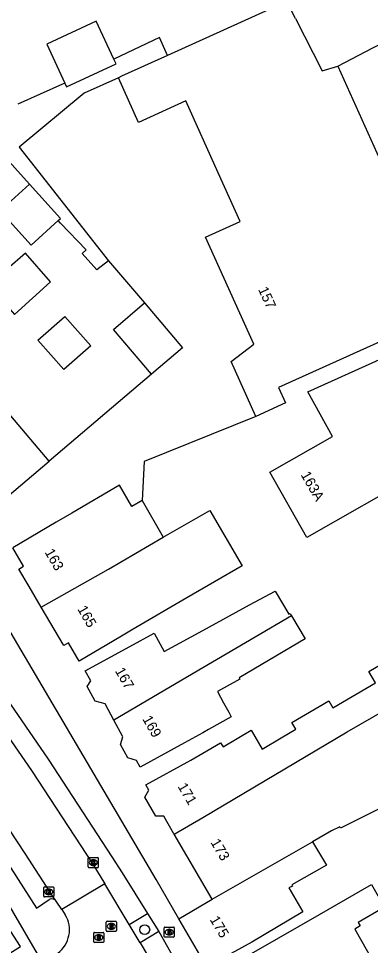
# Model space of a CAD drawing. Extents: x 159888 to 160757, y 384031 to 384746.
# Drawn here: x 160481.8 to 160516.6, y 384336.2 to 384427.7 of the extents above; entities that cross this region are included whole.
import ezdxf

# ---------------------------------------------------------------- set-up
doc = ezdxf.new("R2010")
doc.units = 0
for name, color, linetype in [('IMGEO_Boom', 7, 'Continuous'), ('IMGEO_Brandkraan', 7, 'Continuous'), ('IMGEO_Kolk', 7, 'Continuous'), ('IMGEO_Pand', 7, 'Continuous'), ('IMGEO_Pand_nummerreeks', 7, 'Continuous'), ('IMGEO_Parkeervlak_open', 7, 'Continuous'), ('IMGEO_Rijbaan_lokaal_open', 7, 'Continuous'), ('IMGEO_Rioolput', 7, 'Continuous'), ('IMGEO_Voetpad_open', 7, 'Continuous')]:
    doc.layers.add(name, color=color, linetype=linetype)

msp = doc.modelspace()

# ---------------------------------------------------------------- linework, layer by layer
at = {"layer": 'IMGEO_Boom'}
msp.add_circle((160494.244, 384337.788), 0.489, dxfattribs=at)
at = {"layer": 'IMGEO_Brandkraan'}
for p, q in [((160496.165, 384337.121), (160496.165, 384337.973)), ((160496.24, 384338.047), (160497.092, 384338.047)), ((160496.653, 384337.827), (160496.678, 384337.827)), ((160497.166, 384337.973), (160497.166, 384337.121)), ((160497.092, 384337.047), (160496.24, 384337.047)), ((160496.676, 384337.267), (160496.651, 384337.267))]:
    msp.add_line(p, q, dxfattribs=at)
for points in [[(160496.165, 384337.121), (160496.165, 384337.973)], [(160496.24, 384338.047), (160497.092, 384338.047)], [(160496.513, 384337.747), (160496.513, 384337.347), (160496.726, 384337.347)], [(160496.744, 384337.747), (160496.513, 384337.747)], [(160496.692, 384337.666), (160496.638, 384337.666), (160496.638, 384337.59)], [(160496.638, 384337.59), (160496.691, 384337.59)], [(160496.7, 384337.514), (160496.638, 384337.514), (160496.638, 384337.433)], [(160496.638, 384337.433), (160496.7, 384337.433)], [(160497.166, 384337.973), (160497.166, 384337.121)], [(160497.092, 384337.047), (160496.24, 384337.047)]]:
    msp.add_lwpolyline(points, dxfattribs=at)
for centre, radius, start, end in [((160496.242, 384337.971), 0.0765, 91.55205, 178.44795), ((160496.242, 384337.971), 0.0765, 91.55205, 178.44795), ((160496.693, 384337.628), 0.0379, 267.82845, 90.93552), ((160496.701, 384337.473), 0.0404, 269.87594, 90.50774), ((160496.748, 384337.602), 0.145, 59.4692, 91.53667), ((160496.773, 384337.649), 0.0922, 285.51372, 58.15012), ((160496.778, 384337.457), 0.105, 301.31148, 78.98903), ((160497.09, 384337.971), 0.0765, 1.55205, 88.44795), ((160497.09, 384337.971), 0.0765, 1.55205, 88.44795), ((160496.242, 384337.123), 0.0765, 181.55205, 268.44795), ((160496.242, 384337.123), 0.0765, 181.55205, 268.44795), ((160496.732, 384337.598), 0.251, 268.66757, 293.53466), ((160497.09, 384337.123), 0.0765, 271.55205, 358.44795), ((160497.09, 384337.123), 0.0765, 271.55205, 358.44795)]:
    msp.add_arc(centre, radius, start, end, dxfattribs=at)
for centre, major_axis, ratio, start_param, end_param in [((160496.652, 384337.547), (-0.387, 0.002), 0.722429, 4.712389, 7.853982), ((160496.677, 384337.547), (-0.39, 0.002), 0.717154, 1.570796, 4.712389)]:
    msp.add_ellipse(centre, major_axis=major_axis, ratio=ratio, start_param=start_param, end_param=end_param, dxfattribs=at)
at = {"layer": 'IMGEO_Kolk'}
for p, q in [((160488.659, 384343.984), (160488.659, 384344.836)), ((160488.734, 384344.91), (160489.586, 384344.91)), ((160489.66, 384344.836), (160489.66, 384343.984)), ((160489.586, 384343.91), (160488.734, 384343.91)), ((160489.17, 384344.13), (160489.145, 384344.13)), ((160489.147, 384344.69), (160489.172, 384344.69)), ((160484.336, 384342.021), (160485.188, 384342.021)), ((160484.261, 384341.095), (160484.261, 384341.947)), ((160484.772, 384341.241), (160484.747, 384341.241)), ((160484.749, 384341.801), (160484.774, 384341.801)), ((160485.262, 384341.947), (160485.262, 384341.095)), ((160485.188, 384341.021), (160484.336, 384341.021))]:
    msp.add_line(p, q, dxfattribs=at)
for points in [[(160488.659, 384343.984), (160488.659, 384344.836)], [(160488.734, 384344.91), (160489.586, 384344.91)], [(160489.66, 384344.836), (160489.66, 384343.984)], [(160489.586, 384343.91), (160488.734, 384343.91)], [(160488.98, 384344.61), (160489.103, 384344.61), (160489.103, 384344.459), (160489.233, 384344.61), (160489.397, 384344.61), (160489.251, 384344.459), (160489.404, 384344.21), (160489.252, 384344.21), (160489.167, 384344.374), (160489.103, 384344.307), (160489.103, 384344.21), (160488.98, 384344.21), (160488.98, 384344.61)], [(160484.336, 384342.021), (160485.188, 384342.021)], [(160484.261, 384341.095), (160484.261, 384341.947)], [(160484.582, 384341.721), (160484.705, 384341.721), (160484.705, 384341.57), (160484.835, 384341.721), (160484.999, 384341.721), (160484.853, 384341.57), (160485.006, 384341.321), (160484.854, 384341.321), (160484.769, 384341.485), (160484.705, 384341.418), (160484.705, 384341.321), (160484.582, 384341.321), (160484.582, 384341.721)], [(160485.262, 384341.947), (160485.262, 384341.095)], [(160485.188, 384341.021), (160484.336, 384341.021)]]:
    msp.add_lwpolyline(points, dxfattribs=at)
for centre, start, end in [((160488.736, 384344.834), 91.55205, 178.44795), ((160488.736, 384344.834), 91.55205, 178.44795), ((160489.584, 384344.834), 1.55205, 88.44795), ((160489.584, 384344.834), 1.55205, 88.44795), ((160488.736, 384343.986), 181.55205, 268.44795), ((160488.736, 384343.986), 181.55205, 268.44795), ((160489.584, 384343.986), 271.55205, 358.44795), ((160489.584, 384343.986), 271.55205, 358.44795), ((160484.338, 384341.945), 91.55205, 178.44795), ((160484.338, 384341.945), 91.55205, 178.44795), ((160485.186, 384341.945), 1.55205, 88.44795), ((160485.186, 384341.945), 1.55205, 88.44795), ((160484.338, 384341.097), 181.55205, 268.44795), ((160484.338, 384341.097), 181.55205, 268.44795), ((160485.186, 384341.097), 271.55205, 358.44795), ((160485.186, 384341.097), 271.55205, 358.44795)]:
    msp.add_arc(centre, 0.0765, start, end, dxfattribs=at)
for centre, major_axis, ratio, start_param, end_param in [((160489.146, 384344.41), (-0.387, 0.002), 0.722429, 4.712389, 7.853982), ((160489.171, 384344.41), (-0.39, 0.002), 0.717154, 1.570796, 4.712389), ((160484.748, 384341.521), (-0.387, 0.002), 0.722429, 4.712389, 7.853982), ((160484.773, 384341.521), (-0.39, 0.002), 0.717154, 1.570796, 4.712389)]:
    msp.add_ellipse(centre, major_axis=major_axis, ratio=ratio, start_param=start_param, end_param=end_param, dxfattribs=at)
at = {"layer": 'IMGEO_Pand'}
for points in [[(160509.129, 384427.751), (160508.248, 384429.476), (160507.911, 384429.24), (160496.507, 384424.091)], [(160491.204, 384423.709), (160489.455, 384427.481), (160484.568, 384425.214), (160486.351, 384421.37)], [(160509.129, 384427.751), (160511.769, 384422.587), (160513.319, 384423.031)], [(160513.319, 384423.031), (160516.785, 384424.832), (160519.049, 384426.008)], [(160486.351, 384421.37), (160486.528, 384420.988), (160491.415, 384423.255), (160491.204, 384423.709)], [(160496.507, 384424.091), (160491.96, 384422.038), (160491.637, 384421.892)], [(160513.319, 384423.031), (160517.476, 384413.822)], [(160505.218, 384388.461), (160502.777, 384393.869), (160505.018, 384395.587), (160500.243, 384406.162), (160503.674, 384407.711), (160501.513, 384412.497), (160498.306, 384419.599), (160493.626, 384417.486), (160491.637, 384421.892)], [(160485.695, 384407.79), (160483.023, 384405.371), (160479.952, 384408.762), (160482.855, 384411.39)], [(160485.695, 384407.79), (160485.926, 384407.999), (160482.855, 384411.39)], [(160478.811, 384401.423), (160481.368, 384398.511), (160484.946, 384401.73), (160482.458, 384404.564), (160478.811, 384401.423)], [(160494.904, 384392.62), (160491.151, 384397.042), (160494.231, 384399.656)], [(160494.231, 384399.656), (160497.984, 384395.234), (160494.904, 384392.62)], [(160486.347, 384398.321), (160488.903, 384395.409), (160486.244, 384393.074), (160483.687, 384395.986), (160486.347, 384398.321)], [(160528.944, 384398.447), (160531.06, 384394.011), (160529.854, 384393.381), (160532.476, 384389.133), (160510.261, 384376.495), (160506.59, 384382.948), (160512.814, 384386.489), (160510.357, 384390.876), (160520.089, 384395.264), (160520.242, 384394.924), (160522.66, 384396.015)], [(160522.66, 384396.015), (160521.851, 384397.809), (160507.479, 384391.32), (160508.168, 384389.793), (160505.218, 384388.461)], [(160484.795, 384384.039), (160481.004, 384388.519)], [(160475.174, 384375.922), (160484.795, 384384.039)], [(160493.992, 384380.172), (160492.963, 384379.573), (160491.751, 384381.655), (160487.049, 384378.918), (160485.49, 384378.011), (160481.206, 384375.483)], [(160493.992, 384380.172), (160496.065, 384376.531)], [(160496.065, 384376.531), (160500.691, 384379.183), (160503.875, 384373.713), (160498.413, 384370.534), (160493.098, 384367.44), (160491.959, 384366.777), (160487.774, 384364.286), (160486.707, 384366.106), (160486.241, 384365.833), (160484.01, 384369.637)], [(160484.01, 384369.637), (160490.663, 384373.365), (160496.065, 384376.531)], [(160484.01, 384369.637), (160482.825, 384371.656), (160481.808, 384373.39), (160482.274, 384373.663), (160481.206, 384375.483)], [(160491.205, 384358.458), (160490.321, 384360.076), (160489.362, 384360.357), (160488.572, 384361.803), (160488.911, 384362.359), (160488.37, 384363.35), (160492.759, 384365.747), (160495.173, 384367.066), (160496.173, 384365.235), (160500, 384367.326), (160504.611, 384369.845), (160507.136, 384371.221), (160508.499, 384368.935), (160508.613, 384369.002), (160508.754, 384368.765)], [(160508.754, 384368.765), (160510.108, 384366.495), (160503.576, 384362.635), (160503.641, 384362.517), (160501.427, 384361.308), (160502.033, 384360.198), (160502.553, 384359.247), (160502.799, 384358.796), (160500.557, 384357.541), (160500, 384357.237), (160498.176, 384356.241), (160493.788, 384353.843), (160493.428, 384354.502), (160492.576, 384354.752), (160491.86, 384356.064), (160492.088, 384356.842), (160491.205, 384358.458)], [(160508.754, 384368.765), (160505.142, 384366.671), (160502.29, 384364.99), (160500, 384363.641), (160491.205, 384358.458)], [(160524.795, 384363.386), (160533.053, 384368.196), (160537.917, 384359.917), (160535.784, 384358.855), (160513.593, 384347.808), (160513.509, 384347.952), (160512.702, 384347.561), (160510.827, 384346.464)], [(160497.158, 384347.202), (160497.136, 384347.24), (160496.126, 384348.999), (160495.356, 384348.993), (160494.254, 384350.869), (160494.651, 384351.567), (160494.342, 384352.104), (160498.816, 384354.526), (160500, 384355.222), (160501.744, 384356.246), (160501.979, 384355.846), (160504.763, 384357.481), (160505.858, 384355.619), (160507.732, 384356.72), (160509.179, 384357.57), (160508.781, 384358.247), (160512.43, 384360.391), (160512.836, 384359.7), (160517.045, 384362.172), (160516.387, 384363.292), (160522.679, 384366.989), (160524.795, 384363.386)], [(160497.158, 384347.202), (160500, 384348.872), (160514.234, 384357.32), (160524.795, 384363.386)], [(160500.922, 384340.817), (160497.158, 384347.202)], [(160510.827, 384346.464), (160512.217, 384344.158), (160508.783, 384342.211), (160508.86, 384342.098), (160508.493, 384341.916), (160509.868, 384339.538), (160504.827, 384336.564), (160500.369, 384334.119)], [(160500.922, 384340.817), (160510.827, 384346.464)], [(160500.86, 384333.269), (160503.17, 384334.51), (160507.507, 384336.999), (160511.523, 384339.303), (160516.642, 384342.24), (160517.926, 384340.003), (160515.326, 384338.512), (160515.525, 384338.164), (160514.989, 384337.856), (160516.831, 384334.645), (160514.682, 384333.412)], [(160471.677, 384337.011), (160468.334, 384334.813), (160472.553, 384328.397), (160475.896, 384330.595), (160475.071, 384331.85), (160481.974, 384336.119), (160478.474, 384341.481)], [(160497.6, 384338.863), (160500.922, 384340.817)], [(160500.369, 384334.119), (160497.6, 384338.863)]]:
    msp.add_lwpolyline(points, dxfattribs=at)
at = {"layer": 'IMGEO_Parkeervlak_open'}
for points in [[(160492.705, 384338.303), (160494.523, 384339.39)], [(160495.63, 384337.604), (160493.802, 384336.483)]]:
    msp.add_lwpolyline(points, dxfattribs=at)
at = {"layer": 'IMGEO_Rijbaan_lokaal_open'}
for points in [[(160491.637, 384421.892), (160488.271, 384420.372), (160481.828, 384415.038), (160490.66, 384403.827)], [(160490.66, 384403.827), (160494.231, 384399.656)], [(160494.904, 384392.62), (160484.795, 384384.039)], [(160505.218, 384388.461), (160494.187, 384384.008), (160493.992, 384380.172)], [(160476.066, 384363.585), (160483.044, 384353.5), (160489.12, 384344.263), (160490.303, 384342.319)], [(160485.492, 384340.604), (160485.211, 384341.033), (160482.417, 384345.31), (160479.18, 384350.228), (160475.223, 384356.099)], [(160490.303, 384342.319), (160486.063, 384339.775)], [(160492.705, 384338.303), (160490.303, 384342.319)], [(160486.063, 384339.775), (160485.492, 384340.604)], [(160486.063, 384339.775), (160486.397, 384339.266)], [(160493.802, 384336.483), (160492.705, 384338.303)], [(160493.802, 384336.483), (160495.358, 384333.901)]]:
    msp.add_lwpolyline(points, dxfattribs=at)
msp.add_arc((160483.952, 384337.783), 2.86, 306.27875, 31.241, dxfattribs=at)
at = {"layer": 'IMGEO_Rioolput'}
for p, q in [((160490.449, 384337.694), (160490.449, 384338.546)), ((160490.524, 384338.62), (160491.376, 384338.62)), ((160490.937, 384338.4), (160490.962, 384338.4)), ((160491.45, 384338.546), (160491.45, 384337.694)), ((160489.206, 384336.594), (160489.206, 384337.446)), ((160489.281, 384337.52), (160490.133, 384337.52)), ((160490.207, 384337.446), (160490.207, 384336.594)), ((160491.376, 384337.62), (160490.524, 384337.62)), ((160490.96, 384337.84), (160490.935, 384337.84)), ((160490.133, 384336.52), (160489.281, 384336.52)), ((160489.717, 384336.74), (160489.692, 384336.74)), ((160489.694, 384337.3), (160489.719, 384337.3))]:
    msp.add_line(p, q, dxfattribs=at)
for points in [[(160490.449, 384337.694), (160490.449, 384338.546)], [(160490.524, 384338.62), (160491.376, 384338.62)], [(160491.45, 384338.546), (160491.45, 384337.694)], [(160489.206, 384336.594), (160489.206, 384337.446)], [(160489.281, 384337.52), (160490.133, 384337.52)], [(160490.207, 384337.446), (160490.207, 384336.594)], [(160491.376, 384337.62), (160490.524, 384337.62)], [(160491.038, 384338.318), (160490.786, 384338.32), (160490.786, 384337.92)], [(160490.786, 384337.92), (160490.91, 384337.92), (160490.91, 384338.082), (160490.921, 384338.082)], [(160490.964, 384338.239), (160490.91, 384338.239), (160490.91, 384338.158)], [(160490.91, 384338.158), (160490.962, 384338.158)], [(160490.968, 384338.053), (160491.039, 384337.92), (160491.179, 384337.92), (160491.114, 384338.046)], [(160490.133, 384336.52), (160489.281, 384336.52)], [(160489.795, 384337.218), (160489.543, 384337.22), (160489.543, 384336.82)], [(160489.543, 384336.82), (160489.667, 384336.82), (160489.667, 384336.982), (160489.678, 384336.982)], [(160489.721, 384337.139), (160489.667, 384337.139), (160489.667, 384337.058)], [(160489.667, 384337.058), (160489.719, 384337.058)], [(160489.725, 384336.953), (160489.796, 384336.82), (160489.936, 384336.82), (160489.871, 384336.946)]]:
    msp.add_lwpolyline(points, dxfattribs=at)
for centre, radius, start, end in [((160490.526, 384338.544), 0.0765, 91.55205, 178.44795), ((160490.526, 384338.544), 0.0765, 91.55205, 178.44795), ((160491.374, 384338.544), 0.0765, 1.55205, 88.44795), ((160491.374, 384338.544), 0.0765, 1.55205, 88.44795), ((160489.283, 384337.444), 0.0765, 91.55205, 178.44795), ((160489.283, 384337.444), 0.0765, 91.55205, 178.44795), ((160490.131, 384337.444), 0.0765, 1.55205, 88.44795), ((160490.131, 384337.444), 0.0765, 1.55205, 88.44795), ((160490.526, 384337.696), 0.0765, 181.55205, 268.44795), ((160490.526, 384337.696), 0.0765, 181.55205, 268.44795), ((160490.92, 384338.029), 0.0533, 26.02933, 88.69889), ((160490.946, 384338.347), 0.19, 274.7715, 282.96867), ((160490.97, 384338.143), 0.0964, 77.00612, 93.18647), ((160490.984, 384338.2), 0.0378, 276.66336, 79.67722), ((160491.037, 384338.208), 0.109, 350.36119, 89.41601), ((160491.035, 384338.208), 0.112, 277.58423, 350.98172), ((160491.019, 384337.993), 0.108, 29.51342, 73.79051), ((160491.374, 384337.696), 0.0765, 271.55205, 358.44795), ((160491.374, 384337.696), 0.0765, 271.55205, 358.44795), ((160489.283, 384336.596), 0.0765, 181.55205, 268.44795), ((160489.283, 384336.596), 0.0765, 181.55205, 268.44795), ((160489.677, 384336.929), 0.0533, 26.02933, 88.69889), ((160489.703, 384337.247), 0.19, 274.7715, 282.96867), ((160489.727, 384337.043), 0.0964, 77.00612, 93.18647), ((160489.741, 384337.1), 0.0378, 276.66336, 79.67722), ((160489.794, 384337.108), 0.109, 350.36119, 89.41601), ((160489.792, 384337.108), 0.112, 277.58423, 350.98172), ((160489.776, 384336.893), 0.108, 29.51342, 73.79051), ((160490.131, 384336.596), 0.0765, 271.55205, 358.44795), ((160490.131, 384336.596), 0.0765, 271.55205, 358.44795)]:
    msp.add_arc(centre, radius, start, end, dxfattribs=at)
for centre, major_axis, ratio, start_param, end_param in [((160490.936, 384338.12), (-0.387, 0.002), 0.722429, 4.712389, 7.853982), ((160490.961, 384338.12), (-0.39, 0.002), 0.717154, 1.570796, 4.712389), ((160489.693, 384337.02), (-0.387, 0.002), 0.722429, 4.712389, 7.853982), ((160489.718, 384337.02), (-0.39, 0.002), 0.717154, 1.570796, 4.712389)]:
    msp.add_ellipse(centre, major_axis=major_axis, ratio=ratio, start_param=start_param, end_param=end_param, dxfattribs=at)
at = {"layer": 'IMGEO_Voetpad_open'}
for points in [[(160496.507, 384424.091), (160495.702, 384425.876), (160491.204, 384423.709)], [(160486.351, 384421.37), (160486.13, 384421.264), (160481.72, 384419.27)], [(160482.855, 384411.39), (160478.187, 384416.544), (160472.991, 384416.207), (160471.887, 384415.274)], [(160490.66, 384403.827), (160489.518, 384402.927), (160488.067, 384404.539), (160488.471, 384404.903), (160485.918, 384407.544), (160485.695, 384407.79)], [(160483.657, 384335.415), (160478.945, 384343.45), (160473.633, 384351.562), (160469.711, 384357.202), (160463.306, 384365.649), (160461.477, 384368.06), (160453.348, 384377.769), (160440.266, 384392.474), (160439.728, 384392.001), (160439.463, 384392.301), (160438.349, 384393.558), (160435.261, 384397.057)], [(160497.6, 384338.863), (160495.386, 384342.739), (160478.279, 384371.695)], [(160477.94, 384364.382), (160484.707, 384354.609), (160491.01, 384344.965), (160492.01, 384343.385), (160494.523, 384339.39)], [(160473.831, 384354.68), (160477.646, 384348.946), (160480.98, 384343.914), (160483.555, 384339.925), (160484.813, 384340.767)], [(160494.523, 384339.39), (160495.63, 384337.604)], [(160495.63, 384337.604), (160513.168, 384306.618)]]:
    msp.add_lwpolyline(points, dxfattribs=at)
msp.add_arc((160485.059, 384340.295), 0.532, 35.47113, 117.53103, dxfattribs=at)

# ---------------------------------------------------------------- texts
at = {"layer": 'IMGEO_Pand_nummerreeks'}
for s, rotation, p in [('157', 294.33904, (160505.432, 384400.997)), ('163A', 299.63317, (160509.631, 384382.699)), ('163', 299.93683, (160484.326, 384375.06)), ('165', 299.93683, (160487.561, 384369.443)), ('167', 299.679, (160491.276, 384363.34)), ('169', 299.679, (160493.985, 384358.587)), ('171', 300.53844, (160497.469, 384351.925)), ('173', 300.42958, (160500.716, 384346.413)), ('175', 300.42958, (160500.638, 384338.796))]:
    msp.add_text(s, height=1, rotation=rotation, dxfattribs=at).set_placement(p)

doc.saveas('drawing.dxf')
